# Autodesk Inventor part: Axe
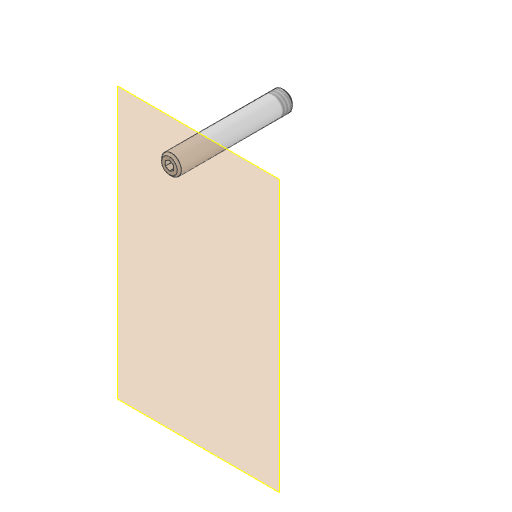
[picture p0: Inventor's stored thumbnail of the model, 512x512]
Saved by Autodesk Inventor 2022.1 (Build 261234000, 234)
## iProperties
Created: 2021-07
Part Number: Axe
Material: Générique
Document SubType Name: Modeling
Designer: Fabian
Density: 1 g/cm^3
Appearance: Par défaut
DocNumber: Axe.ipt
Folder: .\
VDS_Category: Ingénierie
Author: Fabian
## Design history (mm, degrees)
node "Plan de construction1"
sketch "Esquisse1"
  geometry: C1 r 2.5 at (-11.513, 19.133) reference; C2 r 2.4 at (-11.513, 19.133); 1 further point
  constraints: 1 centre point
  dimensions: "d0" = 0.1 radial gap between concentric circles of C1 C2
  node "Référence1"
node "Plan de construction2"
extrude "Extrusion1" new body sketch "Esquisse1" stored distance "d1" = 10; taper "d2" = 0 deg
feature "Filetage1" dims "d3" = 3, "d4" = 0
chamfer "Chanfrein1" distance "d5" = 0.5; stored, may be unused: second distance "d6" = 2, angle "d7" = 45 deg
sketch "Esquisse2"
  geometry: L1 (-1, 0.577)-(0, 1.155); L2 (0, 1.155)-(1, 0.577); L3 (1, 0.577)-(1, -0.577); L4 (1, -0.577)-(0, -1.155); L5 (0, -1.155)-(-1, -0.577); L6 (-1, -0.577)-(-1, 0.577); C1 r 1.9 at (0, 0) reference; 2 further points
  constraints: 12 end point, 1 coincident, 1 vertical, 13 other
  dimensions: "d8" = 2 distance between parallel lines of L2 L5
extrude "Extrusion2" cut sketch "Esquisse2" distance "d9" = 2; taper "d10" = 0 deg
node "Solide1"
node "Boucle projetée1"
